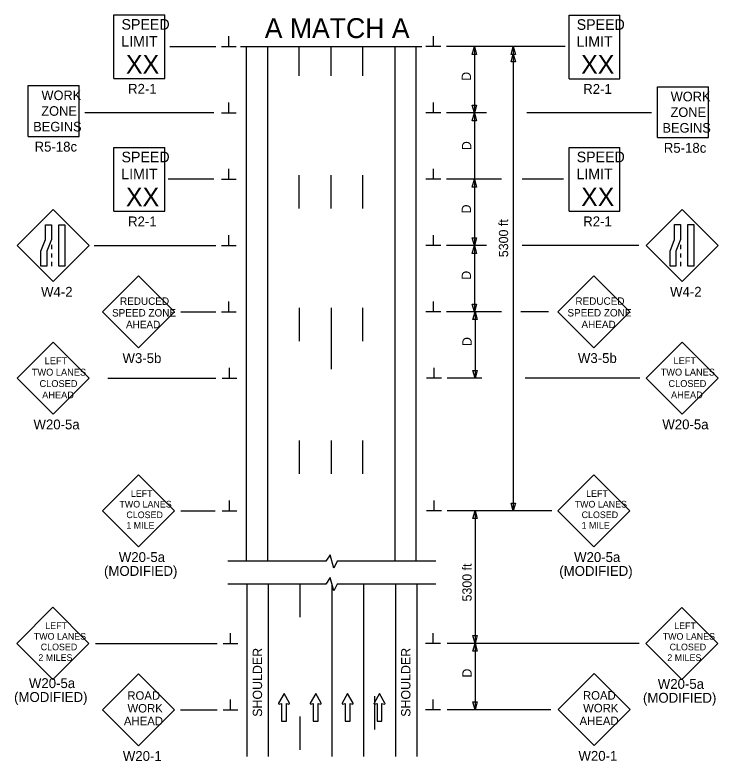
# Model space of a CAD drawing. Extents: x 16486 to 19505, y 5576 to 6998.
# Drawn here: x 17841 to 18371, y 6359 to 6921 of the extents above; entities that cross this region are included whole.
import ezdxf

# ---------------------------------------------------------------- set-up
doc = ezdxf.new("R2010")
doc.units = 0
for name, color, linetype in [('ALI_LEGAL_EX', 7, 'Continuous'), ('MT_SCRATCH_LEVEL_E', 7, 'Continuous'), ('PAVT_EDGE_EX', 7, 'Continuous'), ('TRAFFIC_SIGNS_PR', 7, 'Continuous'), ('TYPICAL_TEXT_DIMEN_PR', 7, 'Continuous')]:
    doc.layers.add(name, color=color, linetype=linetype)

msp = doc.modelspace()

# ---------------------------------------------------------------- linework, layer by layer
at = {"layer": 'ALI_LEGAL_EX'}
for p, q in [((18080.13, 6492.04), (18080.13, 6361.96)), ((18104.13, 6492.04), (18104.13, 6361.96))]:
    msp.add_line(p, q, dxfattribs=at)
for points in [[(18055.61, 6875.22), (18055.61, 6897.24)], [(18079.61, 6875.22), (18079.61, 6897.24)], [(18103.61, 6875.22), (18103.61, 6897.24)], [(18055.61, 6775.22), (18055.61, 6800.22)], [(18079.61, 6775.22), (18079.61, 6800.22)], [(18103.61, 6775.22), (18103.61, 6800.22)], [(18055.61, 6700.22), (18055.61, 6675.22)], [(18079.61, 6700.22), (18079.61, 6675.22)], [(18103.61, 6675.22), (18103.61, 6700.22)], [(18079.61, 6679.08), (18079.61, 6654.08)], [(18055.61, 6600.22), (18055.61, 6575.22)], [(18079.61, 6600.22), (18079.61, 6575.22)], [(18103.61, 6575.22), (18103.61, 6600.22)], [(18056.13, 6492.04), (18056.13, 6467.04)], [(18080.13, 6492.04), (18080.13, 6467.04)], [(18104.13, 6492.04), (18104.13, 6467.04)], [(18112.27, 6407.39), (18112.27, 6382.39)], [(18056.13, 6392.04), (18056.13, 6367.04)], [(18080.13, 6392.04), (18080.13, 6367.04)], [(18104.13, 6392.04), (18104.13, 6367.04)]]:
    msp.add_lwpolyline(points, dxfattribs=at)
at = {"layer": 'MT_SCRATCH_LEVEL_E'}
for p, q in [((18044.13, 6409.47), (18040.02, 6402.23)), ((18048.27, 6402.23), (18044.13, 6409.47)), ((18068.03, 6409.47), (18063.92, 6402.23)), ((18072.18, 6402.23), (18068.03, 6409.47)), ((18092.03, 6409.47), (18087.92, 6402.23)), ((18096.18, 6402.23), (18092.03, 6409.47)), ((18116.08, 6409.47), (18111.97, 6402.23)), ((18120.23, 6402.23), (18116.08, 6409.47)), ((18040.5, 6401.54), (18042.28, 6401.86)), ((18042.28, 6401.86), (18042.28, 6388.6)), ((18046.02, 6388.6), (18046.02, 6401.86)), ((18046.02, 6401.86), (18047.79, 6401.54)), ((18064.4, 6401.54), (18066.18, 6401.86)), ((18066.18, 6401.86), (18066.18, 6388.6)), ((18069.92, 6388.6), (18069.92, 6401.86)), ((18069.92, 6401.86), (18071.7, 6401.54)), ((18088.4, 6401.54), (18090.18, 6401.86)), ((18090.18, 6401.86), (18090.18, 6388.6)), ((18093.92, 6388.6), (18093.92, 6401.86)), ((18093.92, 6401.86), (18095.7, 6401.54)), ((18112.46, 6401.54), (18114.23, 6401.86)), ((18114.23, 6401.86), (18114.23, 6388.6)), ((18117.97, 6388.6), (18117.97, 6401.86)), ((18117.97, 6401.86), (18119.75, 6401.54)), ((18042.28, 6388.6), (18046.02, 6388.6)), ((18066.18, 6388.6), (18069.92, 6388.6)), ((18090.18, 6388.6), (18093.92, 6388.6)), ((18114.23, 6388.6), (18117.97, 6388.6))]:
    msp.add_line(p, q, dxfattribs=at)
for centre, start, end in [((18040.42, 6402), 150.4248, 279.9638), ((18047.86, 6402), 260.0362, 29.7731), ((18064.33, 6402), 150.4248, 279.9638), ((18071.77, 6402), 260.0362, 29.7731), ((18088.33, 6402), 150.4248, 279.9638), ((18095.77, 6402), 260.0362, 29.7731), ((18112.38, 6402), 150.4248, 279.9638), ((18119.82, 6402), 260.0362, 29.7731)]:
    msp.add_arc(centre, 0.463, start, end, dxfattribs=at)
at = {"layer": 'PAVT_EDGE_EX'}
for p, q in [((18015.61, 6897.24), (18015.61, 6509.16)), ((18031.61, 6897.24), (18031.61, 6509.16)), ((18127.61, 6897.24), (18127.61, 6509.16)), ((18143.61, 6897.24), (18143.61, 6509.16)), ((18016.13, 6492.02), (18016.13, 6361.96)), ((18032.13, 6492.02), (18032.13, 6361.96)), ((18128.13, 6492.02), (18128.13, 6361.96)), ((18144.13, 6492.02), (18144.13, 6361.96))]:
    msp.add_line(p, q, dxfattribs=at)
at = {"layer": 'TRAFFIC_SIGNS_PR'}
for p, q in [((17915.82, 6921.16), (17954.22, 6921.16)), ((17915.82, 6873.16), (17915.82, 6921.16)), ((17954.22, 6873.16), (17954.22, 6921.16)), ((18259.02, 6921.06), (18297.42, 6921.06)), ((18259.02, 6873.06), (18259.02, 6921.06)), ((18297.42, 6873.06), (18297.42, 6921.06)), ((17915.82, 6873.16), (17954.22, 6873.16)), ((18259.02, 6873.06), (18297.42, 6873.06)), ((17851.19, 6829.56), (17851.19, 6867.96)), ((17851.19, 6867.96), (17889.59, 6867.96)), ((17889.59, 6829.56), (17889.59, 6867.96)), ((18325.65, 6828.65), (18325.65, 6867.05)), ((18325.65, 6867.05), (18364.05, 6867.05)), ((18364.05, 6828.65), (18364.05, 6867.05)), ((17851.19, 6829.56), (17889.59, 6829.56)), ((18325.65, 6828.65), (18364.05, 6828.65)), ((17915.8, 6821.17), (17954.2, 6821.17)), ((17915.8, 6773.17), (17915.8, 6821.17)), ((17954.2, 6773.17), (17954.2, 6821.17)), ((18259.02, 6821.21), (18297.42, 6821.21)), ((18259.02, 6773.21), (18259.02, 6821.21)), ((18297.42, 6773.21), (18297.42, 6821.21)), ((17869.94, 6774.39), (17842.78, 6747.23)), ((17897.09, 6747.23), (17869.94, 6774.39)), ((17915.8, 6773.17), (17954.2, 6773.17)), ((18259.02, 6773.21), (18297.42, 6773.21)), ((18344.24, 6774.43), (18317.09, 6747.28)), ((18371.39, 6747.28), (18344.24, 6774.43)), ((17842.78, 6747.23), (17869.94, 6720.08)), ((17868.69, 6747.73), (17868.69, 6744.53)), ((17869.94, 6720.08), (17897.09, 6747.23)), ((18317.09, 6747.28), (18344.24, 6720.12)), ((18342.99, 6747.77), (18342.99, 6744.57)), ((18344.24, 6720.12), (18371.39, 6747.28)), ((17868.69, 6741.33), (17868.69, 6738.13)), ((18342.99, 6741.37), (18342.99, 6738.17)), ((17868.69, 6734.93), (17868.69, 6731.73)), ((18342.99, 6734.97), (18342.99, 6731.77)), ((17934.37, 6724.39), (17907.22, 6697.23)), ((17961.52, 6697.23), (17934.37, 6724.39)), ((18277.76, 6724.42), (18250.61, 6697.27)), ((18304.92, 6697.27), (18277.76, 6724.42)), ((17907.22, 6697.23), (17934.37, 6670.08)), ((17934.37, 6670.08), (17961.52, 6697.23)), ((18250.61, 6697.27), (18277.76, 6670.12)), ((18277.76, 6670.12), (18304.92, 6697.27)), ((17870.05, 6674.38), (17842.89, 6647.23)), ((17897.2, 6647.23), (17870.05, 6674.38)), ((18344.23, 6674.42), (18317.08, 6647.27)), ((18371.39, 6647.27), (18344.23, 6674.42)), ((17842.89, 6647.23), (17870.05, 6620.07)), ((17870.05, 6620.07), (17897.2, 6647.23)), ((18317.08, 6647.27), (18344.23, 6620.12)), ((18344.23, 6620.12), (18371.39, 6647.27)), ((17934.4, 6574.42), (17907.21, 6547.24)), ((17961.58, 6547.24), (17934.4, 6574.42)), ((18277.68, 6574.43), (18250.49, 6547.24)), ((18304.87, 6547.24), (18277.68, 6574.43)), ((17907.21, 6547.24), (17934.4, 6520.05)), ((17934.4, 6520.05), (17961.58, 6547.24)), ((18250.49, 6547.24), (18277.68, 6520.05)), ((18277.68, 6520.05), (18304.87, 6547.24)), ((17869.83, 6474.47), (17842.64, 6447.28)), ((17897.02, 6447.28), (17869.83, 6474.47)), ((18344.06, 6474.42), (18316.87, 6447.24)), ((18371.24, 6447.24), (18344.06, 6474.42)), ((17842.64, 6447.28), (17869.83, 6420.1)), ((17869.83, 6420.1), (17897.02, 6447.28)), ((18316.87, 6447.24), (18344.06, 6420.05)), ((18344.06, 6420.05), (18371.24, 6447.24)), ((17934.41, 6424.35), (17907.26, 6397.2)), ((17961.56, 6397.2), (17934.41, 6424.35)), ((18277.96, 6424.44), (18250.81, 6397.29)), ((18305.11, 6397.29), (18277.96, 6424.44)), ((17907.26, 6397.2), (17934.41, 6370.05)), ((17934.41, 6370.05), (17961.56, 6397.2)), ((18250.81, 6397.29), (18277.96, 6370.14)), ((18277.96, 6370.14), (18305.11, 6397.29))]:
    msp.add_line(p, q, dxfattribs=at)
for points in [[(17868.69, 6762.97), (17868.69, 6751.79), (17865.35, 6742.91), (17865.35, 6731.73), (17860.85, 6731.73), (17860.85, 6742.91), (17864.2, 6751.79), (17864.2, 6762.97)], [(17878.83, 6762.97), (17878.83, 6731.73), (17874.33, 6731.73), (17874.33, 6762.97)], [(18342.99, 6763.01), (18342.99, 6751.83), (18339.65, 6742.95), (18339.65, 6731.77), (18335.15, 6731.77), (18335.15, 6742.95), (18338.5, 6751.83), (18338.5, 6763.01)], [(18353.13, 6763.01), (18353.13, 6731.77), (18348.63, 6731.77), (18348.63, 6763.01)]]:
    msp.add_lwpolyline(points, close=True, dxfattribs=at)
at = {"layer": 'TYPICAL_TEXT_DIMEN_PR'}
for p, q in [((18002.48, 6897.24), (18002.48, 6905.02)), ((18156.73, 6897.24), (18156.73, 6905.02)), ((17957.92, 6897.24), (17992.61, 6897.24)), ((17996.86, 6897.24), (18008.11, 6897.24)), ((18011.28, 6897.24), (18147.93, 6897.24)), ((18162.36, 6897.24), (18151.11, 6897.24)), ((18256.12, 6897.24), (18166.61, 6897.24)), ((18186.04, 6891.37), (18187.61, 6897.24)), ((18187.61, 6897.24), (18187.61, 6847.24)), ((18187.61, 6897.24), (18189.18, 6891.37)), ((18215.42, 6891.37), (18216.99, 6897.24)), ((18216.99, 6897.24), (18216.99, 6547.24)), ((18216.99, 6897.24), (18218.56, 6891.37)), ((18187.61, 6891.37), (18186.04, 6891.37)), ((18189.18, 6891.37), (18187.61, 6891.37)), ((18215.42, 6885.87), (18216.99, 6891.73)), ((18216.99, 6891.37), (18215.42, 6891.37)), ((18216.99, 6891.73), (18218.56, 6885.87)), ((18218.56, 6891.37), (18216.99, 6891.37)), ((18216.99, 6885.87), (18215.42, 6885.87)), ((18218.56, 6885.87), (18216.99, 6885.87)), ((18002.48, 6847.24), (18002.48, 6855.02)), ((18156.73, 6847.24), (18156.73, 6855.02)), ((18187.61, 6847.24), (18186.04, 6853.1)), ((18186.04, 6853.1), (18187.61, 6853.1)), ((18187.61, 6853.1), (18189.18, 6853.1)), ((18189.18, 6853.1), (18187.61, 6847.24)), ((17991.11, 6847.24), (17893.92, 6847.24)), ((17996.86, 6847.24), (18008.11, 6847.24)), ((18162.36, 6847.24), (18151.11, 6847.24)), ((18196.69, 6847.24), (18166.61, 6847.24)), ((18186.04, 6841.37), (18187.61, 6847.24)), ((18187.61, 6847.24), (18189.18, 6841.37)), ((18187.61, 6847.24), (18187.61, 6787.24)), ((18321.3, 6847.24), (18227.14, 6847.24)), ((18187.61, 6841.37), (18186.04, 6841.37)), ((18189.18, 6841.37), (18187.61, 6841.37)), ((18002.48, 6797.24), (18002.48, 6805.02)), ((18156.73, 6797.24), (18156.73, 6805.02)), ((17991.11, 6797.24), (17956.73, 6797.24)), ((17996.86, 6797.24), (18008.11, 6797.24)), ((18162.36, 6797.24), (18151.11, 6797.24)), ((18207.99, 6797.24), (18166.61, 6797.24)), ((18186.04, 6791.37), (18187.61, 6797.24)), ((18187.61, 6797.24), (18187.61, 6747.24)), ((18187.61, 6797.24), (18189.18, 6791.37)), ((18254.92, 6797.24), (18223.75, 6797.24)), ((18187.61, 6791.37), (18186.04, 6791.37)), ((18189.18, 6791.37), (18187.61, 6791.37)), ((18002.48, 6747.24), (18002.48, 6755.02)), ((18156.73, 6747.24), (18156.73, 6755.02)), ((18187.61, 6747.24), (18186.04, 6753.1)), ((18186.04, 6753.1), (18187.61, 6753.1)), ((18187.61, 6753.1), (18189.18, 6753.1)), ((18189.18, 6753.1), (18187.61, 6747.24)), ((17900.85, 6747.24), (17992.61, 6747.24)), ((17996.86, 6747.24), (18008.11, 6747.24)), ((18162.36, 6747.24), (18151.11, 6747.24)), ((18196.69, 6747.24), (18166.61, 6747.24)), ((18186.04, 6741.37), (18187.61, 6747.24)), ((18187.61, 6747.24), (18187.61, 6697.24)), ((18187.61, 6747.24), (18189.18, 6741.37)), ((18311.65, 6747.24), (18223.75, 6747.24)), ((18187.61, 6741.37), (18186.04, 6741.37)), ((18189.18, 6741.37), (18187.61, 6741.37)), ((18002.48, 6697.24), (18002.48, 6705.02)), ((18156.73, 6697.24), (18156.73, 6705.02)), ((18187.61, 6697.24), (18186.04, 6703.1)), ((18186.04, 6703.1), (18187.61, 6703.1)), ((18187.61, 6703.1), (18189.18, 6703.1)), ((18189.18, 6703.1), (18187.61, 6697.24)), ((17966.18, 6697.24), (17992.61, 6697.24)), ((17996.86, 6697.24), (18008.11, 6697.24)), ((18162.36, 6697.24), (18151.11, 6697.24)), ((18207.99, 6697.24), (18166.61, 6697.24)), ((18186.56, 6691.37), (18188.13, 6697.24)), ((18188.13, 6697.24), (18188.13, 6647.24)), ((18188.13, 6697.24), (18189.7, 6691.37)), ((18243.52, 6697.24), (18222.62, 6697.24)), ((18188.13, 6691.37), (18186.56, 6691.37)), ((18189.7, 6691.37), (18188.13, 6691.37)), ((18003, 6647.24), (18003, 6655.02)), ((18157.25, 6647.24), (18157.25, 6655.02)), ((18188.13, 6647.24), (18186.56, 6653.1)), ((18186.56, 6653.1), (18188.13, 6653.1)), ((18188.13, 6653.1), (18189.7, 6653.1)), ((18189.7, 6653.1), (18188.13, 6647.24)), ((17911.36, 6647.24), (17992.61, 6647.24)), ((17912.53, 6647.24), (17992.61, 6647.24)), ((17997.38, 6647.24), (18008.63, 6647.24)), ((18162.88, 6647.24), (18151.63, 6647.24)), ((18193.3, 6647.24), (18167.13, 6647.24)), ((18312.49, 6647.24), (18226.01, 6647.24)), ((18003, 6547.24), (18003, 6555.02)), ((18157.25, 6547.24), (18157.25, 6555.02)), ((18216.99, 6547.24), (18215.42, 6553.1)), ((18215.42, 6553.1), (18216.99, 6553.1)), ((18216.99, 6553.1), (18218.56, 6553.1)), ((18218.56, 6553.1), (18216.99, 6547.24)), ((17966.26, 6547.24), (17992.08, 6547.24)), ((17997.38, 6547.24), (18008.63, 6547.24)), ((18162.88, 6547.24), (18151.63, 6547.24)), ((18246.14, 6547.24), (18167.13, 6547.24)), ((18186.56, 6541.37), (18188.13, 6547.24)), ((18188.13, 6547.24), (18188.13, 6447.24)), ((18188.13, 6547.24), (18189.7, 6541.37)), ((18188.13, 6541.37), (18186.56, 6541.37)), ((18189.7, 6541.37), (18188.13, 6541.37)), ((18078.8, 6513.96), (18075.54, 6509.16)), ((18081.54, 6504.02), (18078.8, 6513.96)), ((18075.54, 6509.16), (18001.63, 6509.16)), ((18084.28, 6509.16), (18081.54, 6504.02)), ((18158.63, 6509.16), (18084.28, 6509.16)), ((18078.8, 6496.82), (18075.54, 6492.02)), ((18081.54, 6486.88), (18078.8, 6496.82)), ((18075.54, 6492.02), (18001.63, 6492.02)), ((18084.28, 6492.02), (18081.54, 6486.88)), ((18158.63, 6492.02), (18084.28, 6492.02)), ((18003.75, 6447.24), (18003.75, 6455.02)), ((18156.5, 6447.24), (18156.5, 6455.02)), ((18188.13, 6447.24), (18186.56, 6453.1)), ((18186.56, 6453.1), (18188.13, 6453.1)), ((18188.13, 6453.1), (18189.7, 6453.1)), ((18189.7, 6453.1), (18188.13, 6447.24)), ((17901.83, 6447.08), (17993.62, 6447.08)), ((17998.13, 6447.24), (18009.38, 6447.24)), ((18162.13, 6447.24), (18150.88, 6447.24)), ((18311.79, 6447.24), (18167.13, 6447.24)), ((18186.56, 6441.37), (18188.13, 6447.24)), ((18188.13, 6447.24), (18188.13, 6397.24)), ((18188.13, 6447.24), (18189.7, 6441.37)), ((18188.13, 6441.37), (18186.56, 6441.37)), ((18189.7, 6441.37), (18188.13, 6441.37)), ((18003.75, 6397.24), (18003.75, 6405.02)), ((18156.5, 6397.24), (18156.5, 6405.02)), ((18188.13, 6397.24), (18186.56, 6403.1)), ((18186.56, 6403.1), (18188.13, 6403.1)), ((18188.13, 6403.1), (18189.7, 6403.1)), ((18189.7, 6403.1), (18188.13, 6397.24)), ((17965.93, 6397.24), (17993.62, 6397.24)), ((17998.13, 6397.24), (18009.38, 6397.24)), ((18162.13, 6397.24), (18150.88, 6397.24)), ((18245.39, 6397.24), (18167.13, 6397.24))]:
    msp.add_line(p, q, dxfattribs=at)

# ---------------------------------------------------------------- texts
at = {"layer": 'TRAFFIC_SIGNS_PR'}
for s, height, p in [('SPEED', 8, (17921.58, 6910.03)), ('SPEED', 8, (18264.79, 6909.92)), ('LIMIT', 8, (17921.42, 6897.23)), ('LIMIT', 8, (18264.63, 6897.12)), ('XX', 14.031, (17924.93, 6876.92)), ('XX', 14.031, (18268.14, 6876.82)), ('R2-1', 7.44, (17926.49, 6861.72)), ('R2-1', 7.44, (18269.7, 6861.62)), ('WORK', 7.217, (17861.19, 6856.93)), ('WORK', 7.217, (18335.65, 6856.02)), ('ZONE', 7.217, (17861.07, 6845.12)), ('ZONE', 7.217, (18335.53, 6844.21)), ('BEGINS', 7.217, (17855, 6833.31)), ('BEGINS', 7.217, (18329.46, 6832.4)), ('R5-18c', 7.44, (17856, 6818.12)), ('R5-18c', 7.44, (18330.46, 6817.21)), ('SPEED', 8, (17921.57, 6810.03)), ('SPEED', 8, (18264.79, 6810.08)), ('LIMIT', 8, (17921.41, 6797.23)), ('LIMIT', 8, (18264.63, 6797.28)), ('XX', 14.031, (17924.91, 6776.93)), ('XX', 14.031, (18268.14, 6776.97)), ('R2-1', 7.44, (17926.48, 6761.73)), ('R2-1', 7.44, (18269.7, 6761.77)), ('W4-2', 7.44, (17860.89, 6708.64)), ('W4-2', 7.44, (18335.2, 6708.68)), ('REDUCED', 5.6, (17920.43, 6702.54)), ('REDUCED', 5.6, (18263.82, 6702.58)), ('SPEED ZONE', 5.6, (17914.42, 6693.74)), ('SPEED ZONE', 5.6, (18257.81, 6693.78)), ('AHEAD', 5.6, (17924.98, 6684.94)), ('AHEAD', 5.6, (18268.37, 6684.98)), ('LEFT', 5.2, (17863.59, 6657.76)), ('W3-5b', 7.44, (17922.32, 6658.64)), ('W3-5b', 7.44, (18265.72, 6658.68)), ('LEFT', 5.2, (18337.77, 6657.81)), ('TWO LANES', 5.2, (17853.91, 6649.16)), ('TWO LANES', 5.2, (18328.09, 6649.21)), ('CLOSED', 5.2, (17859.76, 6640.56)), ('CLOSED', 5.2, (18333.95, 6640.61)), ('AHEAD', 5.2, (17861.71, 6631.96)), ('AHEAD', 5.2, (18335.89, 6632.01)), ('W20-5a', 7.44, (17855.19, 6608.63)), ('W20-5a', 7.44, (18329.37, 6608.68)), ('LEFT', 5.006, (17928.64, 6557.73)), ('LEFT', 5.006, (18271.92, 6557.73)), ('TWO LANES', 5.006, (17919.99, 6549.72)), ('TWO LANES', 5.006, (18263.27, 6549.72)), ('CLOSED', 5.006, (17925.22, 6541.71)), ('CLOSED', 5.006, (18268.5, 6541.72)), ('1 MILE', 5.006, (17925.22, 6533.71)), ('1 MILE', 5.006, (18268.5, 6533.71)), ('W20-5a', 7.449, (17919.52, 6508.6)), ('W20-5a', 7.449, (18262.8, 6508.6)), ('(MODIFIED)', 7.449, (17908.36, 6498.15)), ('(MODIFIED)', 7.449, (18251.64, 6498.15)), ('LEFT', 5.006, (17864.07, 6458.08)), ('LEFT', 5.006, (18338.3, 6458.03)), ('TWO LANES', 5.006, (17855.42, 6450.07)), ('TWO LANES', 5.006, (18329.65, 6450.02)), ('CLOSED', 5.006, (17860.66, 6442.06)), ('CLOSED', 5.006, (18334.88, 6442.02)), ('2 MILES', 5.006, (17858.9, 6434.05)), ('2 MILES', 5.006, (18333.13, 6434.01)), ('W20-5a', 7.449, (17851.73, 6413.54)), ('W20-5a', 7.449, (18325.92, 6412.96)), ('(MODIFIED)', 7.449, (17840.57, 6403.09)), ('ROAD', 6.4, (17925.95, 6404.74)), ('ROAD', 6.4, (18269.5, 6404.83)), ('(MODIFIED)', 7.449, (18314.76, 6402.51)), ('WORK', 6.4, (17926.06, 6395.14)), ('WORK', 6.4, (18269.61, 6395.23)), ('AHEAD', 6.4, (17923.37, 6385.54)), ('AHEAD', 6.4, (18266.92, 6385.63)), ('W20-1', 7.44, (17922.58, 6358.61)), ('W20-1', 7.44, (18266.13, 6358.7))]:
    msp.add_text(s, height=height, dxfattribs=at).set_placement(p)
at = {"layer": 'TYPICAL_TEXT_DIMEN_PR'}
msp.add_text('A MATCH A', height=15, dxfattribs=at).set_placement((18029.57, 6903.7))
for s, p in [('D', (18185.05, 6871.45)), ('D', (18185.26, 6819.17)), ('D', (18185.05, 6771.45)), ('5300 ft', (18213.1, 6738.48)), ('D', (18185.05, 6721.45)), ('D', (18185.57, 6671.45)), ('5300 ft', (18185.57, 6478.84)), ('SHOULDER', (18027.55, 6391.89)), ('SHOULDER', (18139.41, 6391.89)), ('D', (18185.57, 6421.46))]:
    msp.add_text(s, height=7, rotation=90, dxfattribs=at).set_placement(p)

doc.saveas('drawing.dxf')
